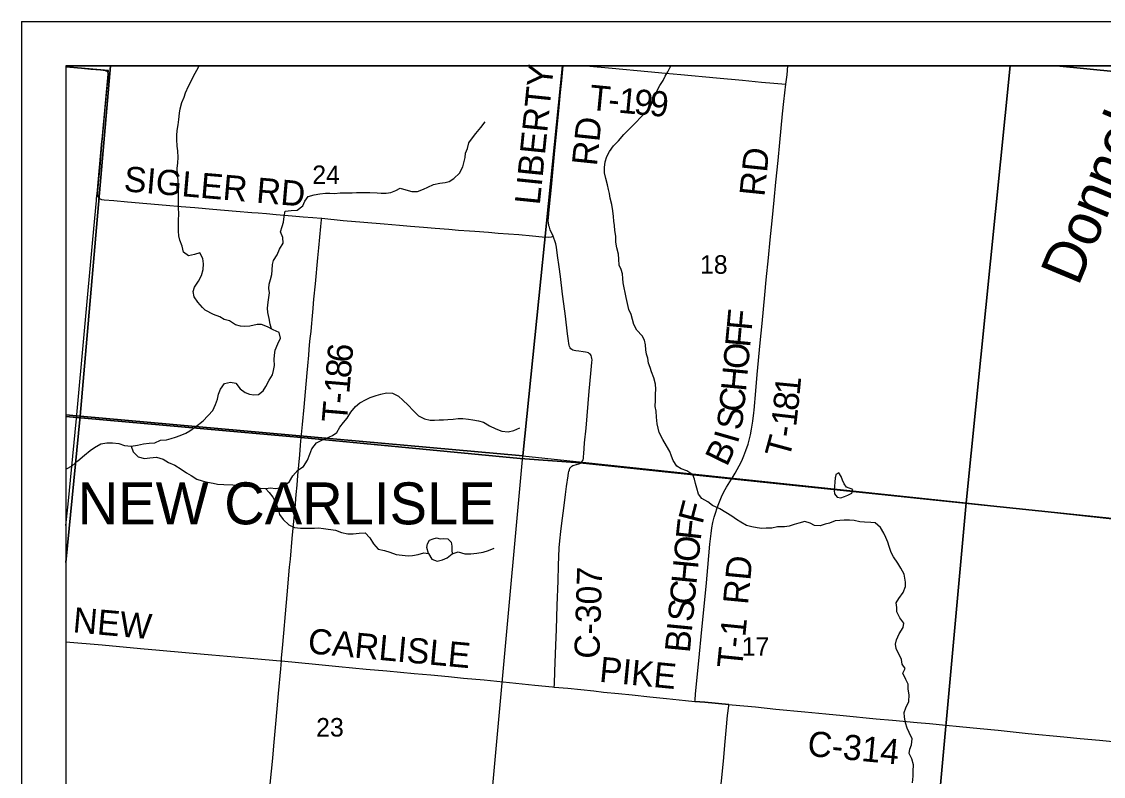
# Model space of a CAD drawing. Extents: x 831 to 1552, y 430 to 870.
# Drawn here: x 1248.77 to 1297.57, y 754.88 to 788.94 of the extents above; entities that cross this region are included whole.
import ezdxf

# ---------------------------------------------------------------- set-up
doc = ezdxf.new("R2010")
doc.units = 0
for name, color, linetype in [('GM_X_Corporation', 7, 'Continuous'), ('GM_X_Corporation_Text', 7, 'Continuous'), ('GM_X_County_Road', 7, 'Continuous'), ('GM_X_County_Road_Text', 7, 'Continuous'), ('GM_X_Minor_Lake', 7, 'Continuous'), ('GM_X_Minor_River', 7, 'Continuous'), ('GM_X_Minor_River_Text', 7, 'Continuous'), ('GM_X_Section_Text', 7, 'Continuous'), ('GM_X_Township_Road', 7, 'Continuous'), ('GM_X_Township_Road_Text', 7, 'Continuous'), ('SH_Data', 7, 'Continuous')]:
    doc.layers.add(name, color=color, linetype=linetype)

msp = doc.modelspace()

# ---------------------------------------------------------------- linework, layer by layer
at = {"layer": 'GM_X_Corporation'}
for points in [[(1252.78, 786.938), (1250.766, 786.938), (1250.766, 771.195), (1251.406, 771.138)], [(1250.766, 786.902), (1250.766, 766.207), (1250.859, 767.156), (1251.24, 771.036), (1251.979, 779.099), (1252.141, 780.861), (1252.147, 780.937), (1252.162, 781.098), (1252.168, 781.163), (1252.387, 783.545), (1252.393, 783.621), (1252.679, 786.732)], [(1273.169, 786.938), (1252.78, 786.938), (1251.406, 771.138), (1271.38, 769.351)], [(1293.37, 786.938), (1273.169, 786.938), (1271.38, 769.351), (1291.379, 767.224)], [(1295.453, 786.938), (1293.37, 786.938), (1291.379, 767.224), (1311.293, 765.037), (1313.248, 785.183)], [(1313.412, 786.938), (1295.453, 786.938), (1313.248, 785.183)], [(1250.766, 771.195), (1250.766, 764.525), (1251.406, 771.138)], [(1250.766, 764.525), (1250.766, 750.702), (1269.535, 749.022), (1271.38, 769.351), (1251.406, 771.138)], [(1271.38, 769.351), (1291.379, 767.224), (1289.554, 747.22), (1269.535, 749.022)], [(1291.379, 767.224), (1311.293, 765.037), (1309.391, 745.383), (1289.554, 747.22)]]:
    msp.add_lwpolyline(points, close=True, dxfattribs=at)
for points in [[(1333.549, 786.938), (1250.766, 786.938), (1250.766, 771.115), (1258.675, 770.41), (1261.379, 770.165), (1271.262, 769.221), (1273.97, 769.031), (1280.784, 768.299), (1307.479, 765.521)], [(1307.479, 765.521), (1280.784, 768.299), (1273.97, 769.031), (1271.262, 769.221), (1261.379, 770.165), (1258.675, 770.41), (1250.766, 771.115), (1250.766, 667.013)]]:
    msp.add_lwpolyline(points, dxfattribs=at)
at = {"layer": 'GM_X_County_Road'}
for points in [[(1272.74, 779.256), (1272.618, 779.542), (1272.574, 779.66), (1272.557, 779.721), (1272.543, 779.782), (1272.534, 779.845), (1272.527, 779.971), (1272.528, 780.102), (1272.559, 780.449), (1272.668, 781.471), (1272.819, 783.126), (1273.004, 784.917), (1273.083, 785.736), (1273.136, 786.277), (1273.196, 786.938)], [(1273.975, 769.02), (1274.002, 769.039), (1274.036, 769.077), (1274.078, 769.13), (1274.093, 769.171), (1274.108, 769.235), (1274.115, 769.311), (1274.123, 769.427), (1274.164, 769.929), (1274.232, 770.589), (1274.371, 772.26), (1274.44, 773.064), (1274.492, 773.558), (1274.498, 773.68), (1274.496, 773.743), (1274.481, 773.815), (1274.458, 773.872), (1274.424, 773.917), (1274.387, 773.954), (1274.334, 773.988), (1274.274, 774.011), (1274.209, 774.026), (1274.104, 774.041), (1273.897, 774.064), (1273.761, 774.083), (1273.689, 774.094), (1273.64, 774.113), (1273.591, 774.143), (1273.55, 774.177), (1273.516, 774.218), (1273.482, 774.282), (1273.463, 774.343), (1273.451, 774.415), (1273.434, 774.54), (1273.4, 774.849), (1273.297, 775.649), (1273.231, 776.205), (1273.173, 776.646), (1273.071, 777.43), (1273.011, 777.878), (1272.947, 778.38), (1272.894, 778.753), (1272.864, 778.911), (1272.826, 779.043), (1272.781, 779.164), (1272.74, 779.256)], [(1272.797, 758.912), (1272.802, 759.046), (1272.826, 759.631), (1272.864, 760.781), (1272.89, 761.527), (1272.924, 762.59), (1272.973, 763.709), (1272.992, 764.403), (1273.022, 765.195), (1273.045, 765.507), (1273.094, 765.937), (1273.153, 766.425), (1273.209, 766.856), (1273.307, 767.594), (1273.354, 767.964), (1273.418, 768.44), (1273.44, 768.581), (1273.456, 768.643), (1273.478, 768.719), (1273.505, 768.783), (1273.542, 768.836), (1273.588, 768.877), (1273.64, 768.907), (1273.697, 768.93), (1273.897, 768.979), (1273.953, 769.005), (1273.975, 769.02)], [(1250.766, 760.948), (1252.398, 760.809), (1254.128, 760.65), (1254.993, 760.57), (1256.164, 760.47), (1257.343, 760.368), (1259.077, 760.214), (1260.103, 760.122), (1260.435, 760.093), (1260.486, 760.088)], [(1260.486, 760.088), (1262.028, 759.938), (1263.079, 759.836), (1264.316, 759.72), (1265.244, 759.641), (1266.48, 759.524), (1267.222, 759.456), (1268.025, 759.381), (1268.706, 759.318), (1269.633, 759.23), (1271.92, 759.003), (1272.723, 758.92), (1272.797, 758.912)], [(1272.797, 758.912), (1273.404, 758.853), (1274.577, 758.733), (1275.01, 758.686), (1275.69, 758.618), (1276.307, 758.554), (1277.11, 758.468), (1277.852, 758.394), (1278.716, 758.303), (1279.142, 758.264)], [(1279.142, 758.264), (1279.582, 758.223), (1280.671, 758.126)], [(1280.671, 758.126), (1280.82, 758.113), (1281.871, 758.011), (1282.798, 757.914), (1284.097, 757.789), (1285.044, 757.707), (1285.828, 757.627), (1287.312, 757.483), (1288.055, 757.415), (1289.166, 757.314), (1289.731, 757.266), (1290.465, 757.198), (1291.083, 757.133), (1292.012, 757.043), (1292.815, 756.958), (1294.175, 756.821), (1295.782, 756.662), (1296.524, 756.591), (1297.391, 756.511), (1298.875, 756.37), (1300.05, 756.259), (1300.461, 756.22)]]:
    msp.add_lwpolyline(points, dxfattribs=at)
at = {"layer": 'GM_X_Minor_Lake'}
for points in [[(1285.477, 768.391), (1285.47, 768.347), (1285.453, 768.157), (1285.443, 767.982), (1285.425, 767.785), (1285.438, 767.625), (1285.558, 767.472), (1285.717, 767.455), (1285.893, 767.506), (1286.045, 767.565), (1286.221, 767.654), (1286.269, 767.82)], [(1286.269, 767.82), (1285.982, 767.923), (1285.87, 768.076), (1285.796, 768.244), (1285.737, 768.412), (1285.64, 768.573), (1285.495, 768.506), (1285.477, 768.391)], [(1267.119, 764.931), (1267.046, 765.206), (1267.079, 765.38), (1267.165, 765.539), (1267.325, 765.598), (1267.477, 765.641), (1267.651, 765.594), (1267.811, 765.607), (1267.993, 765.597), (1268.143, 765.443), (1268.171, 765.261), (1268.177, 765.086), (1268.182, 764.926)], [(1267.119, 764.931), (1267.268, 764.678), (1267.517, 764.592), (1267.754, 764.657), (1267.96, 764.739), (1268.182, 764.926)]]:
    msp.add_lwpolyline(points, dxfattribs=at)
at = {"layer": 'GM_X_Minor_River'}
for points in [[(1257.045, 775.914), (1256.932, 776.044), (1256.708, 776.283), (1256.551, 776.512), (1256.509, 776.764), (1256.572, 776.96), (1256.742, 777.231), (1256.882, 777.488), (1256.961, 777.745), (1256.972, 778.011), (1256.937, 778.254), (1256.811, 778.499), (1256.56, 778.426), (1256.294, 778.369), (1256.076, 778.538), (1256.011, 778.805), (1255.909, 779.072), (1255.858, 779.278), (1255.838, 779.483), (1255.844, 779.969), (1255.855, 780.257), (1255.836, 780.531), (1255.845, 781.245), (1255.841, 781.518), (1255.821, 781.799), (1255.794, 782.027), (1255.79, 782.308), (1255.808, 782.566), (1255.827, 782.809), (1255.808, 783.113), (1255.78, 783.318), (1255.761, 783.615), (1255.763, 783.805), (1255.781, 784.032), (1255.822, 784.282), (1255.863, 784.525), (1255.889, 784.805), (1255.922, 785.002), (1255.987, 785.29), (1256.096, 785.532), (1256.159, 785.728), (1256.292, 786.03), (1256.416, 786.256), (1256.525, 786.475), (1256.672, 786.754), (1256.777, 786.938)], [(1275.292, 783.07), (1275.47, 783.326), (1275.693, 783.559), (1275.932, 783.845), (1276.224, 784.137), (1276.463, 784.37), (1276.709, 784.64), (1276.971, 784.903), (1277.171, 785.182), (1277.273, 785.439), (1277.352, 785.651), (1277.555, 786.058), (1277.709, 786.277), (1277.803, 786.481), (1277.912, 786.677), (1278.028, 786.881), (1278.062, 786.938)], [(1260.035, 775.08), (1259.979, 775.289), (1259.929, 775.548), (1259.879, 775.814), (1259.851, 776.005), (1259.885, 776.278), (1259.917, 776.482), (1259.951, 776.702), (1259.915, 776.9), (1259.94, 777.097), (1259.996, 777.294), (1260.052, 777.522), (1260.07, 777.719), (1260.088, 777.977), (1260.128, 778.166), (1260.291, 778.408), (1260.4, 778.672), (1260.571, 778.936), (1260.551, 779.194), (1260.441, 779.454), (1260.519, 779.689), (1260.575, 779.893), (1260.616, 780.151), (1260.657, 780.386), (1260.931, 780.413), (1261.197, 780.425), (1261.458, 780.627), (1261.536, 780.831), (1261.691, 781.042), (1261.958, 781.122), (1262.217, 781.173), (1262.468, 781.2), (1262.665, 781.198), (1262.885, 781.188), (1263.144, 781.207), (1263.41, 781.219), (1263.676, 781.216), (1263.874, 781.222), (1264.086, 781.227), (1264.284, 781.232), (1264.474, 781.222), (1264.8, 781.218), (1264.99, 781.201), (1265.21, 781.191), (1265.416, 781.234), (1265.645, 781.315), (1265.836, 781.419), (1266.101, 781.347), (1266.373, 781.268), (1266.632, 781.265), (1266.891, 781.376), (1267.09, 781.472), (1267.35, 781.591), (1267.639, 781.648), (1267.868, 781.684), (1268.058, 781.727), (1268.272, 781.861), (1268.519, 782.101), (1268.666, 782.388), (1268.738, 782.623), (1268.778, 782.812), (1268.788, 783.009), (1268.882, 783.206), (1268.938, 783.463), (1269.108, 783.689), (1269.255, 783.885), (1269.486, 784.156), (1269.679, 784.412)], [(1287.071, 766.336), (1286.79, 766.347), (1286.585, 766.373), (1286.327, 766.421), (1286.115, 766.447), (1285.872, 766.442), (1285.682, 766.429), (1285.461, 766.416), (1285.209, 766.313), (1285.019, 766.262), (1284.797, 766.189), (1284.539, 766.199), (1284.343, 766.308), (1284.101, 766.379), (1283.827, 766.307), (1283.613, 766.248), (1283.392, 766.175), (1283.179, 766.147), (1282.86, 766.136), (1282.616, 766.085), (1282.357, 766.073), (1282.167, 766.06), (1281.955, 766.093), (1281.705, 766.134), (1281.463, 766.206), (1281.214, 766.353), (1281.018, 766.477), (1280.799, 766.616), (1280.543, 766.787), (1280.264, 766.949), (1279.932, 767.105), (1279.721, 767.275), (1279.457, 767.423), (1279.3, 767.615), (1279.228, 767.881), (1279.162, 768.095), (1279.119, 768.293), (1279.045, 768.484), (1278.782, 768.662), (1278.525, 768.764), (1278.328, 768.872), (1278.165, 769.133), (1278.083, 769.324), (1278.002, 769.538), (1277.861, 769.798), (1277.698, 770.081), (1277.535, 770.394), (1277.476, 770.592), (1277.433, 770.791), (1277.414, 771.087), (1277.395, 771.353), (1277.352, 771.567), (1277.363, 771.855), (1277.359, 772.121), (1277.377, 772.357), (1277.364, 772.577), (1277.284, 772.859), (1277.189, 773.134), (1277.116, 773.325), (1277.05, 773.523), (1277.014, 773.744), (1276.964, 773.934), (1276.928, 774.125), (1276.916, 774.36), (1276.865, 774.558), (1276.761, 774.765), (1276.521, 775.011), (1276.388, 775.278), (1276.33, 775.492), (1276.264, 775.72), (1276.161, 775.942), (1276.096, 776.224), (1276.038, 776.483), (1275.995, 776.711), (1275.953, 776.932), (1275.91, 777.145), (1275.889, 777.343), (1275.877, 777.556), (1275.818, 777.754), (1275.73, 777.953), (1275.71, 778.226), (1275.698, 778.439), (1275.618, 778.729), (1275.575, 778.98), (1275.571, 779.253), (1275.521, 779.512), (1275.516, 779.733), (1275.488, 779.93), (1275.461, 780.143), (1275.441, 780.394), (1275.391, 780.684), (1275.319, 780.965), (1275.284, 781.179), (1275.248, 781.369), (1275.197, 781.575), (1275.125, 781.856), (1275.067, 782.108), (1275.063, 782.351), (1275.096, 782.609), (1275.168, 782.859), (1275.292, 783.07)], [(1256.961, 770.922), (1257.393, 771.391), (1257.51, 771.664), (1257.604, 771.898), (1257.653, 772.133), (1257.731, 772.36), (1257.924, 772.608), (1258.191, 772.674), (1258.426, 772.618), (1258.62, 772.365), (1258.846, 772.203), (1259.05, 772.124), (1259.247, 772.091), (1259.453, 772.112), (1259.66, 772.277), (1259.784, 772.48), (1259.932, 772.752), (1260.079, 773.001), (1260.135, 773.198), (1260.168, 773.425), (1260.164, 773.691), (1260.174, 773.889), (1260.207, 774.116), (1260.325, 774.396), (1260.449, 774.661), (1260.392, 774.912), (1260.12, 775.037), (1259.863, 775.169), (1259.583, 775.271), (1259.386, 775.273), (1259.066, 775.201), (1258.822, 775.173), (1258.633, 775.198), (1258.413, 775.254), (1258.142, 775.432), (1257.9, 775.496), (1257.704, 775.62), (1257.424, 775.727), (1257.045, 775.914)], [(1256.909, 768.213), (1257.154, 768.157), (1257.412, 768.108), (1257.609, 768.068), (1257.882, 768.057), (1258.292, 768.037), (1258.573, 768.003), (1258.778, 767.971), (1259.044, 767.96), (1259.286, 767.934), (1259.544, 767.886), (1259.787, 767.875), (1259.992, 767.903), (1260.22, 767.87), (1260.41, 767.898), (1260.616, 767.972), (1260.847, 768.19), (1260.994, 768.439), (1261.226, 768.694), (1261.478, 768.866), (1261.657, 769.153), (1261.774, 769.417), (1261.861, 769.667), (1262.062, 769.931), (1262.306, 770.057), (1262.52, 770.138), (1262.787, 770.264), (1262.987, 770.399), (1263.126, 770.64), (1263.289, 770.843), (1263.451, 771.047), (1263.621, 771.311), (1263.822, 771.567), (1264.029, 771.739), (1264.304, 771.888), (1264.495, 771.977), (1264.762, 772.065), (1264.976, 772.123), (1265.22, 772.181), (1265.501, 772.17), (1265.773, 772.038), (1265.968, 771.853), (1266.2, 771.63), (1266.433, 771.384), (1266.673, 771.153), (1266.937, 771.013), (1267.202, 770.949), (1267.392, 770.955), (1267.598, 770.968), (1267.803, 770.973), (1267.993, 770.978), (1268.229, 771.006), (1268.457, 771.026), (1268.677, 771.023), (1268.927, 770.997), (1269.117, 770.972), (1269.375, 770.924), (1269.602, 770.868), (1269.881, 770.705), (1270.16, 770.557), (1270.432, 770.463), (1270.713, 770.422), (1270.972, 770.487), (1271.247, 770.605)], [(1250.766, 768.75), (1250.788, 768.761), (1251.047, 768.894), (1251.3, 769.112), (1251.599, 769.374), (1251.86, 769.591), (1252.059, 769.725), (1252.334, 769.881), (1252.615, 769.931), (1252.865, 769.928), (1253.153, 769.894), (1253.41, 769.807), (1253.705, 769.78), (1253.987, 769.83), (1254.26, 769.88), (1254.526, 769.914), (1254.777, 769.934), (1255.036, 770.052), (1255.302, 770.072), (1255.507, 770.122), (1255.713, 770.18), (1255.911, 770.261), (1256.17, 770.365), (1256.361, 770.469), (1256.606, 770.655), (1256.961, 770.922)], [(1253.705, 769.78), (1253.793, 769.528), (1254.018, 769.298), (1254.305, 769.218), (1254.556, 769.253), (1254.844, 769.28), (1255.154, 769.2), (1255.395, 769.037), (1255.682, 768.92), (1255.96, 768.749), (1256.208, 768.579), (1256.419, 768.454), (1256.667, 768.292), (1256.909, 768.213)], [(1259.764, 767.876), (1259.929, 767.684), (1260.094, 767.484), (1260.205, 767.277), (1260.286, 767.086), (1260.352, 766.881), (1260.403, 766.69), (1260.559, 766.468), (1260.815, 766.237), (1261.079, 766.112), (1261.345, 766.078), (1261.755, 766.074), (1261.975, 766.079), (1262.165, 766.092), (1262.378, 766.066), (1262.924, 765.984), (1263.196, 765.889), (1263.484, 765.818), (1263.719, 765.83), (1263.993, 765.857), (1264.259, 765.869), (1264.469, 765.639), (1264.633, 765.371), (1264.858, 765.132), (1265.13, 765.076), (1265.38, 764.997), (1265.667, 764.887), (1265.94, 764.861), (1266.206, 764.835), (1266.404, 764.841), (1266.655, 764.899), (1266.914, 764.964), (1267.119, 764.931), (1267.268, 764.678), (1267.517, 764.592), (1267.754, 764.657), (1267.96, 764.739), (1268.182, 764.926), (1268.464, 765.006), (1268.767, 764.927), (1269.033, 764.924), (1269.299, 764.951), (1269.581, 765.001), (1269.833, 765.074), (1270.085, 765.185)], [(1288.957, 754.583), (1288.992, 754.887), (1288.994, 755.115), (1289.006, 755.404), (1288.926, 755.671), (1288.8, 755.916), (1288.832, 756.105), (1288.911, 756.31), (1288.937, 756.568), (1288.804, 756.859), (1288.723, 757.05), (1288.642, 757.294), (1288.592, 757.545), (1288.588, 757.766), (1288.659, 757.978), (1288.792, 758.265), (1288.803, 758.554), (1288.768, 758.813), (1288.756, 759.041), (1288.66, 759.255), (1288.527, 759.53), (1288.62, 759.742), (1288.494, 759.941), (1288.458, 760.147), (1288.222, 760.652), (1288.186, 760.842), (1288.234, 761.039), (1288.359, 761.312), (1288.53, 761.591), (1288.563, 761.796), (1288.384, 762.041), (1288.243, 762.309), (1288.253, 762.499), (1288.217, 762.704), (1288.334, 762.908), (1288.535, 763.172), (1288.637, 763.452), (1288.64, 763.642), (1288.576, 764.008), (1288.435, 764.275), (1288.301, 764.505), (1288.107, 764.781), (1287.996, 764.98), (1287.908, 765.247), (1287.85, 765.453), (1287.761, 765.652), (1287.657, 765.85), (1287.516, 766.111), (1287.268, 766.319), (1287.071, 766.336)]]:
    msp.add_lwpolyline(points, dxfattribs=at)
at = {"layer": 'GM_X_Township_Road'}
for points in [[(1250.766, 786.9), (1251.463, 786.835), (1251.882, 786.799), (1252.32, 786.765), (1252.444, 786.752), (1252.507, 786.741), (1252.563, 786.723)], [(1252.563, 786.723), (1252.61, 786.696), (1252.65, 786.641), (1252.664, 786.592), (1252.668, 786.511), (1252.661, 786.402), (1252.6, 785.836), (1252.508, 784.845), (1252.449, 784.164), (1252.376, 783.359), (1252.287, 782.368), (1252.239, 781.81), (1252.186, 781.253), (1252.182, 781.19), (1252.183, 781.162)], [(1274.239, 786.938), (1275.41, 786.832), (1277.018, 786.683), (1277.821, 786.609), (1278.501, 786.547), (1280.109, 786.399), (1281.284, 786.294), (1282.149, 786.213), (1282.706, 786.163), (1283.249, 786.12)], [(1283.249, 786.12), (1283.301, 786.543), (1283.339, 786.938)], [(1281.796, 771.288), (1281.809, 771.407), (1281.89, 772.274), (1281.955, 773.018), (1282.092, 774.442), (1282.178, 775.309), (1282.297, 776.61), (1282.362, 777.291), (1282.455, 778.282), (1282.538, 779.086), (1282.623, 779.953), (1282.718, 780.881), (1282.796, 781.686), (1282.895, 782.676), (1282.97, 783.481), (1283.095, 784.782), (1283.153, 785.338), (1283.249, 786.12)], [(1252.183, 781.162), (1252.183, 781.145), (1252.183, 781.128), (1252.193, 781.067), (1252.218, 781.01), (1252.232, 780.993)], [(1252.232, 780.993), (1252.257, 780.965), (1252.31, 780.934), (1252.369, 780.917), (1252.494, 780.901), (1252.928, 780.863), (1253.547, 780.809), (1254.414, 780.731), (1255.281, 780.654), (1255.962, 780.596), (1256.582, 780.545), (1257.387, 780.477), (1258.44, 780.379), (1259.155, 780.323), (1259.444, 780.306), (1259.82, 780.274), (1260.254, 780.235), (1260.606, 780.201), (1260.978, 780.171), (1261.474, 780.132), (1261.907, 780.098), (1262.278, 780.069), (1262.303, 780.067)], [(1261.384, 770.154), (1261.439, 770.751), (1261.51, 771.546), (1261.571, 772.226), (1261.654, 773.091), (1261.684, 773.4), (1261.722, 773.894), (1261.74, 774.142), (1261.775, 774.512), (1261.796, 774.744), (1261.822, 774.951), (1261.841, 775.151), (1261.858, 775.32), (1261.872, 775.499), (1261.913, 775.993), (1261.933, 776.222), (1261.948, 776.408), (1262.022, 777.101), (1262.134, 778.281), (1262.177, 778.73), (1262.269, 779.697), (1262.297, 779.999), (1262.303, 780.067)], [(1262.303, 780.067), (1263.268, 779.97), (1264.197, 779.891), (1265.126, 779.81), (1265.807, 779.752), (1266.303, 779.707), (1266.896, 779.661), (1267.417, 779.614), (1268.038, 779.569), (1268.471, 779.529), (1268.967, 779.494), (1269.215, 779.478), (1269.834, 779.431), (1270.268, 779.396), (1271.197, 779.326), (1271.817, 779.275), (1272.25, 779.233), (1272.548, 779.214), (1272.671, 779.232), (1272.74, 779.256)], [(1280.789, 768.289), (1280.823, 768.343), (1280.956, 768.569), (1281.14, 768.895), (1281.251, 769.118), (1281.352, 769.346), (1281.443, 769.578), (1281.544, 769.873), (1281.595, 770.054), (1281.651, 770.297), (1281.697, 770.542), (1281.753, 770.912), (1281.796, 771.288)], [(1260.486, 760.088), (1260.497, 760.226), (1260.534, 760.66), (1260.592, 761.341), (1260.668, 762.208), (1260.75, 763.075), (1260.856, 764.314), (1260.891, 764.685), (1260.977, 765.613), (1261.056, 766.543), (1261.099, 766.976), (1261.156, 767.595), (1261.195, 768.027), (1261.234, 768.461), (1261.318, 769.39), (1261.353, 769.823), (1261.369, 770.008), (1261.384, 770.154)], [(1279.142, 758.264), (1279.146, 758.315), (1279.173, 758.605), (1279.316, 760.09), (1279.458, 761.514), (1279.57, 762.69), (1279.661, 763.618), (1279.727, 764.298), (1279.82, 765.352), (1279.868, 765.846), (1279.902, 766.091), (1279.951, 766.334), (1280.014, 766.574), (1280.082, 766.804), (1280.131, 766.956), (1280.185, 767.114), (1280.243, 767.266), (1280.341, 767.492), (1280.45, 767.714), (1280.569, 767.931), (1280.789, 768.289)], [(1259.835, 751.576), (1259.839, 751.826), (1259.838, 751.923), (1259.847, 752.358), (1259.849, 752.855), (1259.862, 753.229), (1259.897, 753.663), (1259.979, 754.53), (1260.093, 755.706), (1260.146, 756.263), (1260.235, 757.254), (1260.298, 757.934), (1260.358, 758.616), (1260.454, 759.731), (1260.486, 760.088)], [(1280.671, 758.126), (1279.582, 758.223), (1279.142, 758.264)], [(1280.292, 754.245), (1280.378, 755.111), (1280.438, 755.727), (1280.489, 756.282), (1280.551, 756.952), (1280.618, 757.628), (1280.665, 758.065), (1280.671, 758.126)]]:
    msp.add_lwpolyline(points, dxfattribs=at)
at = {"layer": 'SH_Data'}
for p, q in [((1248.766, 788.938), (1248.766, 648.938)), ((1248.766, 788.938), (1388.766, 788.938)), ((1250.766, 786.938), (1386.766, 786.938)), ((1250.766, 786.938), (1250.766, 650.938))]:
    msp.add_line(p, q, dxfattribs=at)

# ---------------------------------------------------------------- texts
at = {"layer": 'GM_X_Corporation_Text'}
msp.add_text('NEW CARLISLE', height=1.89394, rotation=0, dxfattribs=at).set_placement((1251.293, 766.252))
at = {"layer": 'GM_X_County_Road_Text'}
for s, rotation, p in [('LIBERTY', 84.1931, (1272.14, 780.635)), ('RD', 84.0923, (1274.716, 782.395)), ('C-307', 88.0712, (1274.828, 760.172)), ('NEW', 354.8867, (1251.048, 761.386)), ('CARLISLE', 354.7144, (1261.647, 760.437)), ('PIKE', 354.4424, (1274.797, 759.153)), ('C-314', 354.4806, (1284.184, 755.811))]:
    msp.add_text(s, height=1.1364, rotation=rotation, dxfattribs=at).set_placement(p)
at = {"layer": 'GM_X_Minor_River_Text'}
msp.add_text('Donnels', height=1.8941, rotation=67.4595, dxfattribs=at).set_placement((1296.434, 776.961))
at = {"layer": 'GM_X_Section_Text'}
for s, p in [('24', (1261.879, 781.608)), ('18', (1279.371, 777.56)), ('17', (1281.254, 760.32)), ('23', (1262.054, 756.676))]:
    msp.add_text(s, height=0.8371, rotation=0, dxfattribs=at).set_placement(p)
at = {"layer": 'GM_X_Township_Road_Text'}
for s, height, rotation, p in [('T', 1.136, 354.4932, (1274.348, 784.962)), ('1', 1.136, 354.5281, (1275.659, 784.835)), ('9', 1.136, 354.6438, (1276.359, 784.768)), ('9', 1.136, 355.0851, (1277.065, 784.702)), ('-', 1.136, 354.4947, (1275.194, 784.88)), ('RD', 1.1364, 84.1354, (1282.276, 781.017)), ('SIGLER RD', 1.1364, 355.104, (1253.349, 781.287)), ('F', 1.136, 84.6563, (1281.699, 774.976)), ('F', 1.136, 84.6563, (1281.628, 774.213)), ('6', 1.136, 84.8202, (1263.666, 773.521)), ('O', 1.136, 84.6613, (1281.535, 773.217)), ('8', 1.136, 85.0868, (1263.606, 772.825)), ('H', 1.136, 84.6538, (1281.442, 772.221)), ('1', 1.136, 85.1387, (1263.547, 772.128)), ('1', 1.136, 84.4875, (1283.859, 772.049)), ('-', 1.136, 85.1391, (1263.507, 771.663)), ('C', 1.136, 84.3947, (1281.35, 771.287)), ('8', 1.136, 84.32, (1283.789, 771.348)), ('T', 1.136, 85.1602, (1263.435, 770.816)), ('S', 1.136, 81.4498, (1281.228, 770.465)), ('1', 1.136, 83.3633, (1283.706, 770.633)), ('-', 1.136, 81.8092, (1283.635, 770.137)), ('B', 1.136, 63.9446, (1280.577, 768.818)), ('I', 1.136, 73.9516, (1281.065, 769.858)), ('T', 1.136, 74.7351, (1283.38, 769.168)), ('F', 1.136, 75.4371, (1279.476, 766.221)), ('F', 1.136, 83.7012, (1279.399, 765.502)), ('O', 1.136, 84.4579, (1279.303, 764.511)), ('RD', 1.1364, 84.5805, (1281.535, 762.603)), ('H', 1.136, 84.4728, (1279.207, 763.515)), ('C', 1.136, 84.4745, (1279.117, 762.586)), ('S', 1.136, 84.4705, (1279.043, 761.823)), ('T-1', 1.1364, 84.3018, (1281.268, 759.723)), ('B', 1.136, 84.4727, (1278.909, 760.43)), ('I', 1.136, 84.4773, (1278.998, 761.359))]:
    msp.add_text(s, height=height, rotation=rotation, dxfattribs=at).set_placement(p)

doc.saveas('drawing.dxf')
